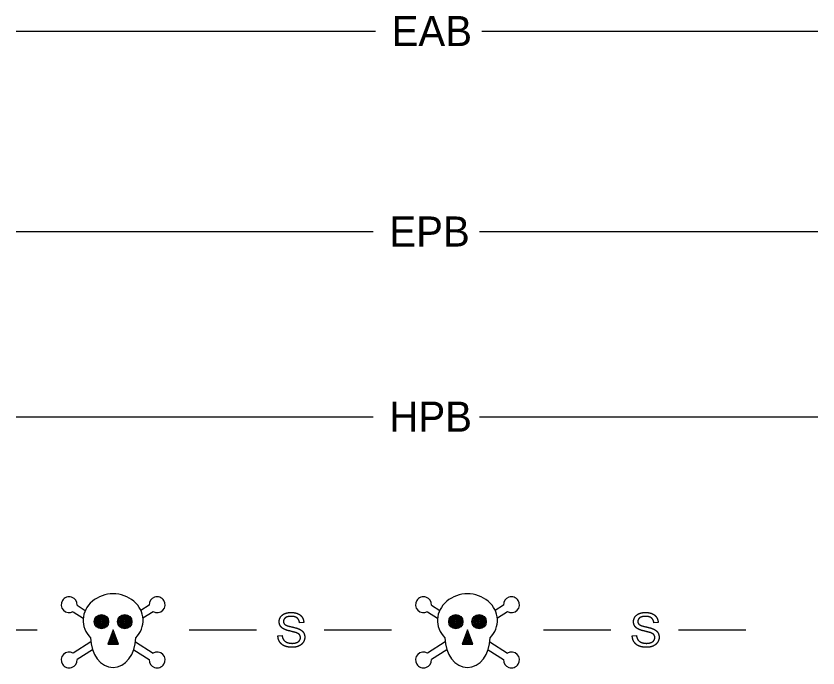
# Model space of a CAD drawing. Extents: x 811508 to 813252, y 647626 to 648754.
# Drawn here: x 811836 to 811918.8, y 648247.1 to 648314.4 of the extents above; entities that cross this region are included whole.
import ezdxf

# ---------------------------------------------------------------- set-up
doc = ezdxf.new("R2010")
doc.units = 0
doc.layers.add('Sheet_Symbology', color=7, linetype='Continuous')

msp = doc.modelspace()

# ---------------------------------------------------------------- linework, layer by layer
at = {"layer": 'Sheet_Symbology'}
for p, q in [((811835.963, 648312.895), (811873.079, 648312.895)), ((811884.05, 648312.895), (811918.76, 648312.895)), ((811835.963, 648292.196), (811872.846, 648292.196)), ((811883.817, 648292.196), (811918.76, 648292.196)), ((811835.963, 648273.077), (811872.846, 648273.077)), ((811883.817, 648273.077), (811918.76, 648273.077)), ((811842.271, 648253.599), (811843.116, 648253.068)), ((811849.7, 648253.599), (811848.855, 648253.068)), ((811878.857, 648253.599), (811879.702, 648253.068)), ((811886.286, 648253.599), (811885.441, 648253.068)), ((811841.857, 648252.941), (811842.901, 648252.285)), ((811850.113, 648252.941), (811849.07, 648252.285)), ((811878.444, 648252.941), (811879.487, 648252.285)), ((811886.7, 648252.941), (811885.656, 648252.285)), ((811865.671, 648251.821), (811865.231, 648251.787)), ((811902.258, 648251.821), (811901.817, 648251.787)), ((811835.963, 648251.059), (811838.146, 648251.059)), ((811853.825, 648251.059), (811860.794, 648251.059)), ((811867.763, 648251.059), (811874.732, 648251.059)), ((811890.411, 648251.059), (811897.38, 648251.059)), ((811904.349, 648251.059), (811911.318, 648251.059)), ((811845.985, 648250.806), (811845.985, 648250.806)), ((811863, 648250.438), (811863.435, 648250.475)), ((811882.572, 648250.806), (811882.572, 648250.806)), ((811899.586, 648250.438), (811900.021, 648250.475)), ((811843.679, 648249.815), (811841.857, 648248.67)), ((811848.291, 648249.815), (811850.113, 648248.67)), ((811880.266, 648249.815), (811878.444, 648248.67)), ((811884.877, 648249.815), (811886.7, 648248.67)), ((811843.855, 648249.008), (811842.271, 648248.012)), ((811848.116, 648249.008), (811849.7, 648248.012)), ((811880.441, 648249.008), (811878.857, 648248.012)), ((811884.702, 648249.008), (811886.286, 648248.012))]:
    msp.add_line(p, q, dxfattribs=at)
for points in [[(811845.985, 648251.059), (811845.44, 648249.568), (811846.531, 648249.568)], [(811882.572, 648251.059), (811882.026, 648249.568), (811883.117, 648249.568)], [(811845.985, 648250.806), (811845.564, 648249.655), (811846.407, 648249.655)], [(811845.985, 648250.552), (811845.689, 648249.742), (811846.282, 648249.742)], [(811845.985, 648250.299), (811845.813, 648249.829), (811846.157, 648249.829)], [(811845.985, 648250.045), (811845.938, 648249.916), (811846.033, 648249.916)], [(811882.572, 648250.806), (811882.15, 648249.655), (811882.993, 648249.655)], [(811882.572, 648250.552), (811882.275, 648249.742), (811882.868, 648249.742)], [(811882.572, 648250.299), (811882.4, 648249.829), (811882.743, 648249.829)], [(811882.572, 648250.045), (811882.524, 648249.916), (811882.619, 648249.916)]]:
    msp.add_lwpolyline(points, close=True, dxfattribs=at)
for centre, radius in [((811844.785, 648251.907), 0.739), ((811844.785, 648251.907), 0.652), ((811847.186, 648251.907), 0.739), ((811847.186, 648251.907), 0.652), ((811881.371, 648251.907), 0.739), ((811881.371, 648251.907), 0.652), ((811883.772, 648251.907), 0.739), ((811883.772, 648251.907), 0.652), ((811844.785, 648251.907), 0.564), ((811844.785, 648251.907), 0.477), ((811844.785, 648251.907), 0.39), ((811844.785, 648251.907), 0.303), ((811844.785, 648251.907), 0.216), ((811844.785, 648251.907), 0.129), ((811844.785, 648251.907), 0.0418), ((811847.186, 648251.907), 0.564), ((811847.186, 648251.907), 0.477), ((811847.186, 648251.907), 0.39), ((811847.186, 648251.907), 0.303), ((811847.186, 648251.907), 0.216), ((811847.186, 648251.907), 0.129), ((811847.186, 648251.907), 0.0418), ((811881.371, 648251.907), 0.564), ((811881.371, 648251.907), 0.477), ((811881.371, 648251.907), 0.39), ((811881.371, 648251.907), 0.303), ((811881.371, 648251.907), 0.216), ((811881.371, 648251.907), 0.129), ((811881.371, 648251.907), 0.0418), ((811883.772, 648251.907), 0.564), ((811883.772, 648251.907), 0.477), ((811883.772, 648251.907), 0.39), ((811883.772, 648251.907), 0.303), ((811883.772, 648251.907), 0.216), ((811883.772, 648251.907), 0.129), ((811883.772, 648251.907), 0.0418)]:
    msp.add_circle(centre, radius, dxfattribs=at)
for centre, start, end in [((811841.447, 648253.658), 355.89762, 299.80617), ((811850.524, 648253.658), 240.19383, 184.10238), ((811878.033, 648253.658), 355.89762, 299.80617), ((811887.11, 648253.658), 240.19383, 184.10238), ((811841.447, 648247.953), 60.19383, 4.10238), ((811850.524, 648247.953), 175.89762, 119.80617), ((811878.033, 648247.953), 60.19383, 4.10238), ((811887.11, 648247.953), 175.89762, 119.80617)]:
    msp.add_arc(centre, 0.826, start, end, dxfattribs=at)
for centre, major_axis, ratio, start_param, end_param in [((811845.985, 648252.038), (3.097, 0), 0.885014, 5.564242, 10.143721), ((811882.572, 648252.038), (3.097, 0), 0.885014, 5.564242, 10.143721), ((811845.985, 648250.265), (0, -3.097), 0.752542, 4.722735, 7.843636), ((811882.572, 648250.265), (0, -3.097), 0.752542, 4.722735, 7.843636)]:
    msp.add_ellipse(centre, major_axis=major_axis, ratio=ratio, start_param=start_param, end_param=end_param, dxfattribs=at)
for points in [[(811863.28, 648252.395), (811863.43, 648252.624), (811863.718, 648252.743)], [(811863.718, 648252.743), (811864.006, 648252.862), (811864.359, 648252.862)], [(811864.359, 648252.862), (811864.747, 648252.862), (811865.044, 648252.738)], [(811865.044, 648252.738), (811865.34, 648252.613), (811865.5, 648252.37)], [(811899.866, 648252.395), (811900.016, 648252.624), (811900.304, 648252.743)], [(811900.304, 648252.743), (811900.593, 648252.862), (811900.945, 648252.862)], [(811900.945, 648252.862), (811901.333, 648252.862), (811901.63, 648252.738)], [(811901.63, 648252.738), (811901.926, 648252.613), (811902.086, 648252.37)], [(811863.13, 648251.901), (811863.13, 648252.165), (811863.28, 648252.395)], [(811863.252, 648251.467), (811863.13, 648251.661), (811863.13, 648251.901)], [(811863.766, 648252.302), (811863.573, 648252.149), (811863.573, 648251.933)], [(811863.573, 648251.933), (811863.573, 648251.745), (811863.709, 648251.623)], [(811864.378, 648252.456), (811863.958, 648252.456), (811863.766, 648252.302)], [(811864.988, 648252.287), (811864.782, 648252.456), (811864.378, 648252.456)], [(811865.231, 648251.787), (811865.195, 648252.118), (811864.988, 648252.287)], [(811865.5, 648252.37), (811865.66, 648252.128), (811865.671, 648251.821)], [(811899.716, 648251.901), (811899.716, 648252.165), (811899.866, 648252.395)], [(811899.838, 648251.467), (811899.716, 648251.661), (811899.716, 648251.901)], [(811900.352, 648252.302), (811900.159, 648252.149), (811900.159, 648251.933)], [(811900.159, 648251.933), (811900.159, 648251.745), (811900.296, 648251.623)], [(811900.964, 648252.456), (811900.544, 648252.456), (811900.352, 648252.302)], [(811901.574, 648252.287), (811901.368, 648252.456), (811900.964, 648252.456)], [(811901.817, 648251.787), (811901.781, 648252.118), (811901.574, 648252.287)], [(811902.086, 648252.37), (811902.246, 648252.128), (811902.258, 648251.821)], [(811863.624, 648251.143), (811863.375, 648251.273), (811863.252, 648251.467)], [(811864.299, 648250.925), (811863.817, 648251.04), (811863.624, 648251.143)], [(811863.709, 648251.623), (811863.843, 648251.502), (811864.408, 648251.375)], [(811864.923, 648250.755), (811864.782, 648250.81), (811864.299, 648250.925)], [(811864.408, 648251.375), (811864.973, 648251.247), (811865.182, 648251.152)], [(811865.182, 648251.152), (811865.485, 648251.012), (811865.63, 648250.797)], [(811900.21, 648251.143), (811899.961, 648251.273), (811899.838, 648251.467)], [(811900.885, 648250.925), (811900.403, 648251.04), (811900.21, 648251.143)], [(811900.296, 648251.623), (811900.429, 648251.502), (811900.994, 648251.375)], [(811901.509, 648250.755), (811901.368, 648250.81), (811900.885, 648250.925)], [(811900.994, 648251.375), (811901.559, 648251.247), (811901.768, 648251.152)], [(811901.768, 648251.152), (811902.072, 648251.012), (811902.216, 648250.797)], [(811863.191, 648249.811), (811863.009, 648250.088), (811863, 648250.438)], [(811863.435, 648250.475), (811863.466, 648250.213), (811863.579, 648250.045)], [(811863.579, 648250.045), (811863.692, 648249.877), (811863.93, 648249.774)], [(811865.237, 648250.549), (811865.142, 648250.672), (811864.923, 648250.755)], [(811865.233, 648249.964), (811865.331, 648250.101), (811865.331, 648250.263)], [(811865.331, 648250.263), (811865.331, 648250.427), (811865.237, 648250.549)], [(811865.775, 648250.302), (811865.775, 648250.024), (811865.616, 648249.778)], [(811865.63, 648250.797), (811865.775, 648250.582), (811865.775, 648250.302)], [(811899.777, 648249.811), (811899.595, 648250.088), (811899.586, 648250.438)], [(811900.021, 648250.475), (811900.052, 648250.213), (811900.165, 648250.045)], [(811900.165, 648250.045), (811900.278, 648249.877), (811900.516, 648249.774)], [(811901.823, 648250.549), (811901.728, 648250.672), (811901.509, 648250.755)], [(811901.819, 648249.964), (811901.918, 648250.101), (811901.918, 648250.263)], [(811901.918, 648250.263), (811901.918, 648250.427), (811901.823, 648250.549)], [(811902.361, 648250.302), (811902.361, 648250.024), (811902.202, 648249.778)], [(811902.216, 648250.797), (811902.361, 648250.582), (811902.361, 648250.302)], [(811863.693, 648249.396), (811863.373, 648249.534), (811863.191, 648249.811)], [(811864.486, 648249.258), (811864.013, 648249.258), (811863.693, 648249.396)], [(811863.93, 648249.774), (811864.168, 648249.67), (811864.465, 648249.67)], [(811864.465, 648249.67), (811864.73, 648249.67), (811864.932, 648249.749)], [(811865.158, 648249.395), (811864.859, 648249.258), (811864.486, 648249.258)], [(811864.932, 648249.749), (811865.134, 648249.827), (811865.233, 648249.964)], [(811865.616, 648249.778), (811865.456, 648249.532), (811865.158, 648249.395)], [(811900.279, 648249.396), (811899.959, 648249.534), (811899.777, 648249.811)], [(811901.072, 648249.258), (811900.599, 648249.258), (811900.279, 648249.396)], [(811900.516, 648249.774), (811900.754, 648249.67), (811901.052, 648249.67)], [(811901.052, 648249.67), (811901.316, 648249.67), (811901.518, 648249.749)], [(811901.744, 648249.395), (811901.446, 648249.258), (811901.072, 648249.258)], [(811901.518, 648249.749), (811901.72, 648249.827), (811901.819, 648249.964)], [(811902.202, 648249.778), (811902.042, 648249.532), (811901.744, 648249.395)]]:
    msp.add_open_spline(points, degree=2, dxfattribs=at)

# ---------------------------------------------------------------- texts
for s, p in [('EAB', (811874.735, 648311.343)), ('EPB', (811874.502, 648290.644)), ('HPB', (811874.502, 648271.524))]:
    msp.add_text(s, height=3.1049, dxfattribs=at).set_placement(p)

doc.saveas('drawing.dxf')
